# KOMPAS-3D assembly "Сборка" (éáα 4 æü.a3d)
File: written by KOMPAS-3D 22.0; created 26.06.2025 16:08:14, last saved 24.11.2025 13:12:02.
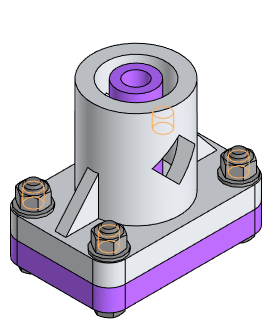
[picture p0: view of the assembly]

Document properties: Автор: Helen; Полное имя файла: C:\Для ноута\Инженерная графика\ППЭ 2025-2026\Варианты 1-38\Вариант 4 СБ\Вар 4 СБ\Вар 4 СБ.a3d

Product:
- Component [detail]: Основание  | designation Вариант 4  | qty 1  | Масса: 2.685762; source file: Основание вар4.m3d
- Component [detail]: Nodes  | qty 1  | Масса: 3.975239; source file: Корпус вар 4.m3d
- Component [detail]: Болт М14x60 ГОСТ 15591-70  | qty 4  | Масса: 0.091885; source file: Болт М14x60 ГОСТ 15591-70.m3d
- Component [detail]: Сборка  | qty 4  | Масса: 0.008612; source file: Шайба 14.m3d
- Component [detail]: Сборка  | qty 4  | Масса: 0.02533; source file: Гайка М14.m3d
- Part/product: Сборка
    Масса: 7.164307

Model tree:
1. Массив по сетке:1  (with: Операция без истории:1, Элемент выдавливания:3, Элемент выдавливания:1)  (4 pattern instances)
     Шаг 1 = 120; Угол раствора = 90; Шаг 2 = 70

Referenced files in C:\Для ноута\Инженерная графика\ППЭ 2025-2026\Варианты 1-38\Вариант 4 СБ\Вар 4 СБ\: Основание вар4.m3d, Корпус вар 4.m3d, Болт М14x60 ГОСТ 15591-70.m3d, Шайба 14.m3d, Гайка М14.m3d
Referenced files in D:\MY\WORK\MPEI\ППЭ_2025-2026\Варианты\Вар 4 СБ\: Болт М14x60 ГОСТ 15591-70.m3d, Гайка М14.m3d, Шайба 14.m3d
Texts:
  Вариант 4 Основание
  Болт М14x60 ГОСТ 15591-70 (1)
  Сборка (1)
